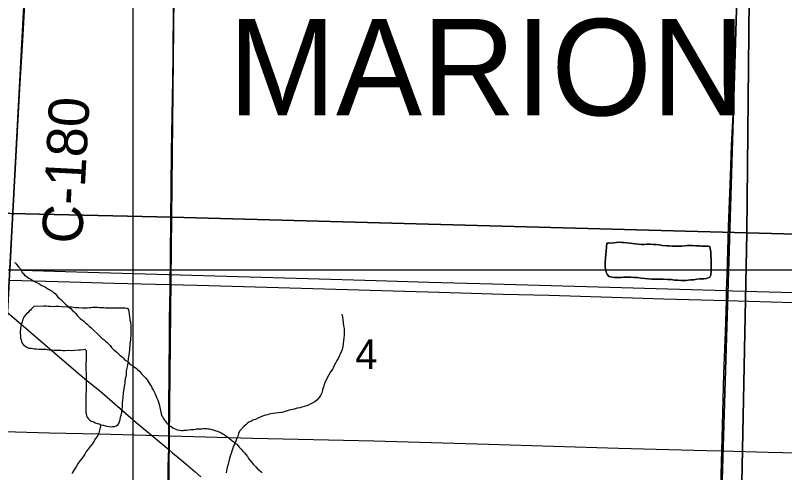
# Model space of a CAD drawing. Extents: x 0 to 68, y 0 to 52.9.
# Drawn here: x 45.735 to 47.168, y 36.885 to 37.738 of the extents above; entities that cross this region are included whole.
import ezdxf

# ---------------------------------------------------------------- set-up
doc = ezdxf.new("R2010")
doc.units = 0
for name, color, linetype in [('Default', 7, 'Continuous'), ('GM_X_County_Road', 7, 'Continuous'), ('GM_X_County_Road_Text', 7, 'Continuous'), ('GM_X_Minor_Lake', 7, 'Continuous'), ('GM_X_Minor_River', 7, 'Continuous'), ('GM_X_State_Route', 7, 'Continuous'), ('GM_X_Township_Text', 7, 'Continuous')]:
    doc.layers.add(name, color=color, linetype=linetype)

msp = doc.modelspace()

# ---------------------------------------------------------------- linework, layer by layer
at = {"layer": 'Default'}
for p, q in [((45.9541, 31.1431), (45.9541, 38.5351)), ((41.1051, 37.2633), (50.3451, 37.2633))]:
    msp.add_line(p, q, dxfattribs=at)
for points in [[(44.9606, 38.4445), (46.0367, 38.4191), (46.0251, 37.3614), (44.9603, 37.3859)], [(46.0367, 38.4191), (47.1078, 38.3881), (47.0974, 37.332), (46.0251, 37.3614)], [(47.1078, 38.3881), (48.1729, 38.3556), (48.157, 37.3036), (47.0974, 37.332)], [(44.4103, 37.9396), (44.4523, 37.939), (45.7586, 37.9073), (45.6896, 36.6248), (44.3441, 36.6667)], [(45.7586, 37.9073), (45.7821, 37.907), (47.0815, 37.8719), (47.0429, 36.5865), (45.6896, 36.6248)], [(47.0815, 37.8719), (47.106, 37.8711), (48.4264, 37.8391), (48.3843, 36.5523), (47.0429, 36.5865)], [(44.9603, 37.3859), (46.0251, 37.3614), (46.0139, 36.3013), (44.9528, 36.3285)], [(46.0251, 37.3614), (47.0974, 37.332), (47.0762, 36.2748), (46.0139, 36.3013)], [(47.0974, 37.332), (48.157, 37.3036), (48.1401, 36.2463), (47.0762, 36.2748)]]:
    msp.add_lwpolyline(points, close=True, dxfattribs=at)
at = {"layer": 'GM_X_County_Road'}
for points in [[(45.7251, 37.2633), (45.7304, 37.3716), (45.7431, 37.601), (45.7485, 37.6911), (45.7525, 37.7689), (45.7589, 37.8795), (45.7596, 37.8883), (45.7609, 37.9018), (45.7615, 37.9082)], [(47.0596, 37.2244), (47.0604, 37.2537), (47.0634, 37.3439), (47.0666, 37.4382), (47.0689, 37.4954), (47.0722, 37.5653), (47.0743, 37.6267), (47.0786, 37.7503), (47.0809, 37.8112), (47.0822, 37.8338), (47.0831, 37.8446), (47.0839, 37.8519), (47.0855, 37.859), (47.0872, 37.8628), (47.0898, 37.8678), (47.0923, 37.8714), (47.0961, 37.8759)], [(46.0201, 36.9281), (46.0201, 36.9712), (46.0204, 37.0073), (46.0218, 37.1385), (46.0218, 37.1713), (46.023, 37.227), (46.0241, 37.3549), (46.0256, 37.4829), (46.0276, 37.6174), (46.0283, 37.6633), (46.0288, 37.7551)], [(47.0591, 37.2059), (47.0596, 37.2244)], [(47.0506, 36.9255), (47.0547, 37.0692), (47.0575, 37.1471), (47.0591, 37.2059)], [(45.7088, 36.962), (45.7137, 36.9618), (45.7979, 36.959), (45.8899, 36.9572), (46.177, 36.9495), (46.4026, 36.9442), (46.6159, 36.9382), (46.8579, 36.9307), (47.0219, 36.9262), (47.0506, 36.9255)], [(46.0084, 35.9707), (46.0092, 36.0429), (46.0101, 36.1611), (46.0112, 36.2595), (46.0121, 36.335), (46.014, 36.4433), (46.0148, 36.5353), (46.0157, 36.6732), (46.0161, 36.7093), (46.0171, 36.775), (46.0184, 36.8209), (46.0189, 36.8471), (46.0194, 36.8931), (46.0199, 36.916), (46.0201, 36.9281)], [(47.026, 35.9278), (47.0267, 35.9621), (47.0286, 36.0646), (47.0329, 36.2368), (47.0354, 36.3311), (47.0374, 36.4173), (47.0402, 36.5526), (47.0424, 36.6305), (47.045, 36.7248), (47.0467, 36.7781), (47.05, 36.9052), (47.0506, 36.9255)], [(47.0506, 36.9255), (47.1368, 36.9232), (47.3008, 36.9196), (47.3869, 36.9168), (47.5633, 36.912), (47.6576, 36.9082), (47.6945, 36.9078), (47.7642, 36.9104), (47.8052, 36.9099), (48.0964, 36.9016), (48.2236, 36.898), (48.2717, 36.8956), (48.3187, 36.8931), (48.3966, 36.8871)]]:
    msp.add_lwpolyline(points, dxfattribs=at)
at = {"layer": 'GM_X_Minor_Lake'}
for points in [[(46.8364, 37.313), (46.8374, 37.313), (46.8394, 37.313), (46.842, 37.3135), (46.8455, 37.313), (46.8495, 37.3135), (46.8545, 37.314), (46.8595, 37.3145), (46.8645, 37.3144), (46.8685, 37.3139), (46.8736, 37.3134), (46.8896, 37.3119), (46.8946, 37.3113), (46.9001, 37.3103), (46.9057, 37.3103), (46.9112, 37.3108), (46.9172, 37.3108), (46.9227, 37.3107), (46.9282, 37.3102), (46.9343, 37.3097), (46.9398, 37.3087), (46.9473, 37.3082), (46.9528, 37.3081), (46.9583, 37.3076), (46.9628, 37.3071), (46.9669, 37.3071), (46.9719, 37.3076), (46.9764, 37.3076), (46.9814, 37.3081), (46.9859, 37.3085), (46.9904, 37.3085), (46.996, 37.3085), (47.002, 37.308), (47.006, 37.308), (47.0095, 37.308), (47.0125, 37.3074), (47.0155, 37.3074), (47.019, 37.3074), (47.0226, 37.3074), (47.0251, 37.3074), (47.0281, 37.3069), (47.0291, 37.3024), (47.0296, 37.2999), (47.0301, 37.2969), (47.03, 37.2928), (47.03, 37.2888), (47.0305, 37.2843), (47.0305, 37.2813), (47.0305, 37.2778), (47.0305, 37.2748), (47.0305, 37.2713), (47.0305, 37.2683), (47.0305, 37.2597), (47.03, 37.2557), (47.03, 37.2532), (47.0284, 37.2497), (47.0254, 37.2482), (47.0219, 37.2472), (47.0174, 37.2467), (47.0099, 37.2463), (47.0043, 37.2458), (46.9983, 37.2448), (46.9928, 37.2443), (46.9878, 37.2438), (46.9838, 37.2433), (46.9793, 37.2433), (46.9742, 37.2434), (46.9687, 37.2439), (46.9627, 37.2439), (46.9562, 37.2449), (46.9497, 37.2454), (46.9416, 37.2455), (46.9361, 37.2455), (46.9311, 37.2455), (46.9256, 37.246), (46.9201, 37.246), (46.914, 37.2466), (46.9075, 37.2471), (46.9005, 37.2476), (46.8935, 37.2486), (46.887, 37.2487), (46.8809, 37.2492), (46.8739, 37.2497), (46.8684, 37.2492), (46.8634, 37.2487), (46.8599, 37.2487), (46.8564, 37.2488), (46.8533, 37.2488), (46.8508, 37.2488), (46.8463, 37.2493), (46.8403, 37.2508), (46.8368, 37.2548), (46.8353, 37.2589), (46.8348, 37.2619), (46.8338, 37.2644), (46.8333, 37.2694), (46.8333, 37.2774), (46.8364, 37.313)], [(46.8364, 37.313), (46.8333, 37.2774), (46.8333, 37.2694), (46.8338, 37.2644), (46.8348, 37.2619), (46.8353, 37.2589), (46.8368, 37.2548), (46.8403, 37.2508), (46.8463, 37.2493), (46.8508, 37.2488), (46.8533, 37.2488), (46.8564, 37.2488), (46.8599, 37.2487), (46.8634, 37.2487), (46.8684, 37.2492), (46.8739, 37.2497), (46.8809, 37.2492), (46.887, 37.2487), (46.8935, 37.2486), (46.9005, 37.2476), (46.9075, 37.2471), (46.914, 37.2466), (46.9201, 37.246), (46.9256, 37.246), (46.9311, 37.2455), (46.9361, 37.2455), (46.9416, 37.2455), (46.9497, 37.2454), (46.9562, 37.2449), (46.9627, 37.2439), (46.9687, 37.2439), (46.9742, 37.2434), (46.9793, 37.2433), (46.9838, 37.2433), (46.9878, 37.2438), (46.9928, 37.2443), (46.9983, 37.2448), (47.0043, 37.2458), (47.0099, 37.2463), (47.0174, 37.2467), (47.0219, 37.2472), (47.0254, 37.2482), (47.0284, 37.2497), (47.03, 37.2532), (47.03, 37.2557), (47.0305, 37.2597), (47.0305, 37.2683), (47.0305, 37.2713), (47.0305, 37.2748), (47.0305, 37.2778)], [(47.0305, 37.2778), (47.0305, 37.2813), (47.0305, 37.2843), (47.03, 37.2888), (47.03, 37.2928), (47.0301, 37.2969), (47.0296, 37.2999), (47.0291, 37.3024), (47.0281, 37.3069), (47.0251, 37.3074), (47.0226, 37.3074), (47.019, 37.3074), (47.0155, 37.3074), (47.0125, 37.3074), (47.0095, 37.308), (47.006, 37.308), (47.002, 37.308), (46.996, 37.3085), (46.9904, 37.3085), (46.9859, 37.3085), (46.9814, 37.3081), (46.9764, 37.3076), (46.9719, 37.3076), (46.9669, 37.3071), (46.9628, 37.3071), (46.9583, 37.3076), (46.9528, 37.3081), (46.9473, 37.3082), (46.9398, 37.3087), (46.9343, 37.3097), (46.9282, 37.3102), (46.9227, 37.3107), (46.9172, 37.3108), (46.9112, 37.3108), (46.9057, 37.3103), (46.9001, 37.3103), (46.8946, 37.3113), (46.8896, 37.3119), (46.8736, 37.3134), (46.8685, 37.3139), (46.8645, 37.3144), (46.8595, 37.3145), (46.8545, 37.314), (46.8495, 37.3135), (46.8455, 37.313), (46.842, 37.3135), (46.8394, 37.313), (46.8374, 37.313), (46.8364, 37.313)], [(45.7697, 37.1949), (45.769, 37.1945), (45.7645, 37.1905), (45.7625, 37.188), (45.76, 37.186), (45.7575, 37.183), (45.755, 37.181), (45.7509, 37.176), (45.7489, 37.1715), (45.7479, 37.169), (45.7469, 37.1665), (45.7449, 37.158), (45.7439, 37.1545), (45.7439, 37.152), (45.7433, 37.1485), (45.7433, 37.1445), (45.7438, 37.1399), (45.7443, 37.1359), (45.7453, 37.1329), (45.7458, 37.1299), (45.7468, 37.1269), (45.7498, 37.1234), (45.7523, 37.1213), (45.7558, 37.1188), (45.7598, 37.1173), (45.7638, 37.1168), (45.7669, 37.1163), (45.7694, 37.1158), (45.7734, 37.1158), (45.7774, 37.1152), (45.7819, 37.1152), (45.7864, 37.1152), (45.7914, 37.1152), (45.7974, 37.1142), (45.8025, 37.1142), (45.8065, 37.1136), (45.8105, 37.1131), (45.815, 37.1131), (45.819, 37.1131), (45.823, 37.1126), (45.8275, 37.1126), (45.8326, 37.1131), (45.8386, 37.113), (45.8451, 37.1135), (45.8521, 37.114), (45.8561, 37.114), (45.8612, 37.1145), (45.8642, 37.115), (45.8662, 37.1125), (45.8667, 37.1089), (45.8667, 37.1059), (45.8667, 37.1019), (45.8666, 37.0994), (45.8666, 37.0964), (45.8661, 37.0934), (45.8656, 37.0899), (45.8656, 37.0864), (45.8656, 37.0839), (45.8656, 37.0809), (45.8656, 37.0778), (45.8656, 37.0753), (45.8661, 37.0718), (45.8661, 37.0673), (45.8666, 37.0628), (45.8666, 37.0583), (45.8665, 37.0548), (45.8665, 37.0518), (45.8665, 37.0477), (45.8665, 37.0442), (45.8665, 37.0407), (45.8665, 37.0362), (45.866, 37.0317), (45.866, 37.0272), (45.866, 37.0227), (45.866, 37.0191), (45.866, 37.0156), (45.8659, 37.0116), (45.8659, 37.0086), (45.8659, 37.0056), (45.8659, 37.0021), (45.8659, 36.9986), (45.8664, 36.9941), (45.8669, 36.9911), (45.8684, 36.9885), (45.8704, 36.986), (45.8734, 36.983), (45.8759, 36.981), (45.8804, 36.9795), (45.8834, 36.978), (45.8874, 36.9769), (45.8904, 36.9759), (45.894, 36.9744), (45.898, 36.9734), (45.9025, 36.9724), (45.905, 36.9714), (45.9095, 36.9709), (45.912, 36.9703), (45.9155, 36.9708), (45.919, 36.9713), (45.9225, 36.9723)], [(45.9225, 36.9723), (45.9251, 36.9738), (45.9271, 36.9768), (45.9286, 36.9803), (45.9296, 36.9843), (45.9306, 36.9883), (45.9316, 36.9924), (45.9321, 36.9949), (45.9326, 36.9979), (45.9337, 37.0039), (45.9342, 37.0079), (45.9342, 37.0114), (45.9342, 37.0154), (45.9347, 37.0199), (45.9352, 37.0239), (45.9352, 37.0275), (45.9357, 37.031), (45.9362, 37.0335), (45.9367, 37.038), (45.9383, 37.049), (45.9388, 37.0525), (45.9393, 37.0555), (45.9398, 37.0585), (45.9398, 37.0611), (45.9408, 37.0641), (45.9413, 37.0676), (45.9413, 37.0706), (45.9418, 37.0736), (45.9424, 37.0771), (45.9434, 37.0821), (45.9439, 37.0861), (45.9444, 37.0896), (45.9449, 37.0926), (45.9454, 37.0956), (45.9454, 37.0982), (45.9459, 37.1012), (45.9464, 37.1047), (45.9474, 37.1092), (45.948, 37.1132), (45.948, 37.1172), (45.9485, 37.1217), (45.9485, 37.1257), (45.949, 37.1287), (45.9495, 37.1323), (45.9495, 37.1363), (45.95, 37.1403), (45.95, 37.1443), (45.95, 37.1478), (45.9501, 37.1513), (45.9501, 37.1548), (45.9501, 37.1578), (45.9501, 37.1608), (45.9496, 37.1654), (45.9486, 37.1689), (45.9481, 37.1724), (45.9476, 37.1764), (45.9471, 37.1799), (45.9466, 37.1849), (45.9456, 37.189), (45.9426, 37.191), (45.9391, 37.1915), (45.9351, 37.1915), (45.9326, 37.1915), (45.9296, 37.1915), (45.9251, 37.1915), (45.922, 37.1915), (45.9195, 37.1915), (45.9165, 37.1916), (45.914, 37.1916), (45.9115, 37.1916), (45.9085, 37.1916), (45.9055, 37.1916), (45.9025, 37.1916), (45.899, 37.1921), (45.8955, 37.1921), (45.8914, 37.1921), (45.8874, 37.1927), (45.8819, 37.1927), (45.8784, 37.1927), (45.8754, 37.1922), (45.8724, 37.1922), (45.8689, 37.1917), (45.8644, 37.1917), (45.8588, 37.1917), (45.8528, 37.1923), (45.8458, 37.1923), (45.8388, 37.1933), (45.8317, 37.1938), (45.8217, 37.1944), (45.8152, 37.1949), (45.8097, 37.1949), (45.8047, 37.1944), (45.8001, 37.1949), (45.7961, 37.195), (45.7921, 37.1955), (45.7876, 37.1955), (45.7697, 37.1949)]]:
    msp.add_lwpolyline(points, dxfattribs=at)
at = {"layer": 'GM_X_Minor_River'}
for points in [[(45.733, 37.2771), (45.7354, 37.2759), (45.7369, 37.2734), (45.7405, 37.2686), (45.7441, 37.2653), (45.7453, 37.2621), (45.7472, 37.2584), (45.7492, 37.2568), (45.7516, 37.2535), (45.7544, 37.2511), (45.7572, 37.2494), (45.7596, 37.2478), (45.762, 37.2466), (45.7644, 37.2449), (45.7676, 37.2429), (45.7716, 37.2408), (45.7752, 37.2392), (45.7784, 37.2375), (45.7836, 37.2338), (45.788, 37.2322), (45.7904, 37.2309), (45.7928, 37.2293), (45.796, 37.2272), (45.7984, 37.226), (45.8004, 37.2248), (45.8028, 37.2231), (45.8056, 37.2211), (45.8084, 37.219), (45.8112, 37.2162), (45.8139, 37.2125), (45.8183, 37.2085), (45.8235, 37.2036), (45.8279, 37.1991), (45.8322, 37.1954), (45.8358, 37.1926), (45.8382, 37.1905), (45.8406, 37.1877), (45.8438, 37.1848), (45.847, 37.1816), (45.8505, 37.1771)], [(45.8505, 37.1771), (45.8553, 37.1726), (45.8621, 37.1673), (45.8653, 37.1645), (45.8681, 37.162), (45.8709, 37.1596), (45.8729, 37.1575), (45.8752, 37.1555), (45.8776, 37.153), (45.88, 37.1506), (45.8884, 37.1433), (45.8904, 37.1404), (45.8932, 37.1384), (45.8955, 37.1359), (45.8991, 37.1331), (45.9027, 37.1302), (45.9055, 37.1274), (45.9083, 37.1249), (45.9111, 37.1221), (45.9139, 37.1184), (45.9174, 37.1148), (45.9206, 37.1119), (45.9234, 37.1095), (45.9266, 37.1066), (45.9294, 37.1042), (45.9314, 37.1021), (45.9334, 37.1009), (45.9354, 37.0993), (45.9373, 37.0968), (45.9401, 37.094), (45.9425, 37.0927), (45.9445, 37.0907), (45.9477, 37.087), (45.9513, 37.0854), (45.9533, 37.0841), (45.9565, 37.0817), (45.9593, 37.0797), (45.9621, 37.0772), (45.9657, 37.0739), (45.9692, 37.0695), (45.9736, 37.0646), (45.9776, 37.0609), (45.98, 37.0581), (45.9819, 37.0548), (45.9839, 37.052), (45.9859, 37.0484), (45.9879, 37.0455), (45.989, 37.0427), (45.991, 37.0391), (45.993, 37.0358), (45.9941, 37.033), (45.9961, 37.0289), (45.9981, 37.0241), (46, 37.0201), (46.0016, 37.0148), (46.0031, 37.0104), (46.0039, 37.0063), (46.0054, 36.9979), (46.0062, 36.9947), (46.0069, 36.9914), (46.0085, 36.989), (46.0101, 36.9866), (46.0125, 36.9829), (46.014, 36.9809), (46.016, 36.9777), (46.02, 36.974), (46.0228, 36.9719), (46.0248, 36.9707), (46.028, 36.9683), (46.0304, 36.9674), (46.0332, 36.9662), (46.0368, 36.9649), (46.0408, 36.9641), (46.044, 36.9636), (46.0469, 36.9636), (46.0489, 36.964), (46.0513, 36.9639), (46.0537, 36.9643), (46.0573, 36.9647), (46.0614, 36.9654), (46.065, 36.9654), (46.067, 36.9657), (46.0707, 36.9661), (46.0727, 36.9665), (46.0759, 36.9668), (46.0791, 36.9668), (46.0815, 36.9668), (46.0848, 36.9671), (46.088, 36.9671), (46.0904, 36.967), (46.0932, 36.9666), (46.0964, 36.9666), (46.0988, 36.9661), (46.1049, 36.9644), (46.1081, 36.9632), (46.1109, 36.9623), (46.1137, 36.9611), (46.1161, 36.9603), (46.1181, 36.9594), (46.1213, 36.9574), (46.1237, 36.9558)], [(46.343, 37.1807), (46.3434, 37.1777), (46.3444, 37.1711), (46.3449, 37.1646), (46.3459, 37.1586), (46.3469, 37.1536), (46.3469, 37.148), (46.3469, 37.142), (46.3464, 37.136), (46.3458, 37.1305), (46.3453, 37.1255), (46.3448, 37.12), (46.3433, 37.1144), (46.3423, 37.1114), (46.3398, 37.1059), (46.3378, 37.1019), (46.3357, 37.0979), (46.3337, 37.0939), (46.3307, 37.0894), (46.3282, 37.0849), (46.3257, 37.0784), (46.3216, 37.0729), (46.3186, 37.0674), (46.3151, 37.0619), (46.3126, 37.0564), (46.3105, 37.0518), (46.309, 37.0463), (46.307, 37.0403), (46.306, 37.0353), (46.304, 37.0313), (46.303, 37.0288), (46.3005, 37.0248), (46.2964, 37.0203), (46.2924, 37.0168), (46.2874, 37.0143), (46.2824, 37.0118), (46.2773, 37.0098), (46.2728, 37.0083), (46.2683, 37.0068), (46.2643, 37.0058), (46.2593, 37.0054), (46.2537, 37.0034), (46.2447, 37.0014), (46.2372, 36.9989), (46.2307, 36.9974), (46.2246, 36.9964), (46.2196, 36.996), (46.2146, 36.995), (46.2106, 36.9945), (46.2076, 36.994), (46.2041, 36.993), (46.2005, 36.992), (46.197, 36.991), (46.1915, 36.989), (46.1865, 36.9865), (46.182, 36.984), (46.1769, 36.9825), (46.1729, 36.9805), (46.1694, 36.9791), (46.1664, 36.9766), (46.1639, 36.9741), (46.1604, 36.9711), (46.1523, 36.9626), (46.1503, 36.958), (46.1493, 36.9545), (46.1473, 36.9495), (46.1452, 36.9435), (46.1427, 36.938), (46.1402, 36.9325), (46.1382, 36.927), (46.1367, 36.9205), (46.1346, 36.9155), (46.1331, 36.9089), (46.1301, 36.8984), (46.1286, 36.8919), (46.127, 36.8849)], [(45.894, 36.9744), (45.8894, 36.9564), (45.8869, 36.9524), (45.8839, 36.9484), (45.8808, 36.9429), (45.8773, 36.9378), (45.8733, 36.9333), (45.8693, 36.9283), (45.8667, 36.9243), (45.8637, 36.9193), (45.8602, 36.9138), (45.8552, 36.9078), (45.8516, 36.9028), (45.8481, 36.8973), (45.8451, 36.8923), (45.8431, 36.8883), (45.8411, 36.8853), (45.8396, 36.8828)], [(46.1237, 36.9558), (46.1269, 36.9537), (46.1301, 36.9512), (46.1337, 36.9484), (46.1377, 36.9447), (46.1417, 36.9423), (46.1444, 36.9394), (46.1468, 36.9378), (46.1488, 36.9357), (46.1516, 36.9325), (46.1552, 36.9288), (46.1584, 36.9252), (46.1611, 36.9219), (46.1639, 36.9187), (46.1667, 36.915), (46.1691, 36.9114), (46.1714, 36.9081), (46.1742, 36.9045), (46.1774, 36.9008), (46.1798, 36.8984), (46.1822, 36.8955), (46.1853, 36.8923), (46.1889, 36.8894), (46.1921, 36.887), (46.1945, 36.8845)]]:
    msp.add_lwpolyline(points, dxfattribs=at)
at = {"layer": 'GM_X_State_Route'}
for points in [[(45.5248, 37.3507), (45.5357, 37.3406), (45.5607, 37.3194), (45.5855, 37.2979), (45.6306, 37.2599), (45.6704, 37.2256), (45.8075, 37.1085), (45.8474, 37.0745), (45.8673, 37.0574), (45.8911, 37.038), (45.9588, 36.9791), (45.9915, 36.9525), (46.0201, 36.9281), (46.0274, 36.9219)], [(45.7251, 37.2633), (45.89, 37.2584), (46.2794, 37.247), (46.4065, 37.2435), (46.5048, 37.2404), (46.6237, 37.237), (46.8204, 37.2313), (46.9721, 37.2269), (47.0596, 37.2244), (47.0705, 37.2241), (47.2303, 37.2194)], [(45.7241, 37.2441), (45.8358, 37.2407), (45.9179, 37.2386), (46.0731, 37.2347), (46.2248, 37.2302), (46.5242, 37.2214), (46.6431, 37.218), (46.7292, 37.2158), (46.9425, 37.2093), (47.0591, 37.2059), (47.1844, 37.2022), (47.4468, 37.1944), (47.6396, 37.1887), (47.807, 37.1841), (47.8639, 37.182), (48.0784, 37.1764), (48.144, 37.175), (48.2629, 37.1711), (48.3141, 37.1697)], [(46.0274, 36.9219), (46.0518, 36.9011), (46.0693, 36.8862), (46.0798, 36.8771)]]:
    msp.add_lwpolyline(points, dxfattribs=at)

# ---------------------------------------------------------------- texts
at = {"layer": 'Default'}
msp.add_text('4', height=0.0553, rotation=0, dxfattribs=at).set_placement((46.3678, 37.0784))
at = {"layer": 'GM_X_County_Road_Text'}
msp.add_text('C-180', height=0.075, rotation=86.9706, dxfattribs=at).set_placement((45.8584, 37.3106))
at = {"layer": 'GM_X_Township_Text'}
msp.add_text('MARION', height=0.18, rotation=0, dxfattribs=at).set_placement((46.1313, 37.5511))

doc.saveas('drawing.dxf')
